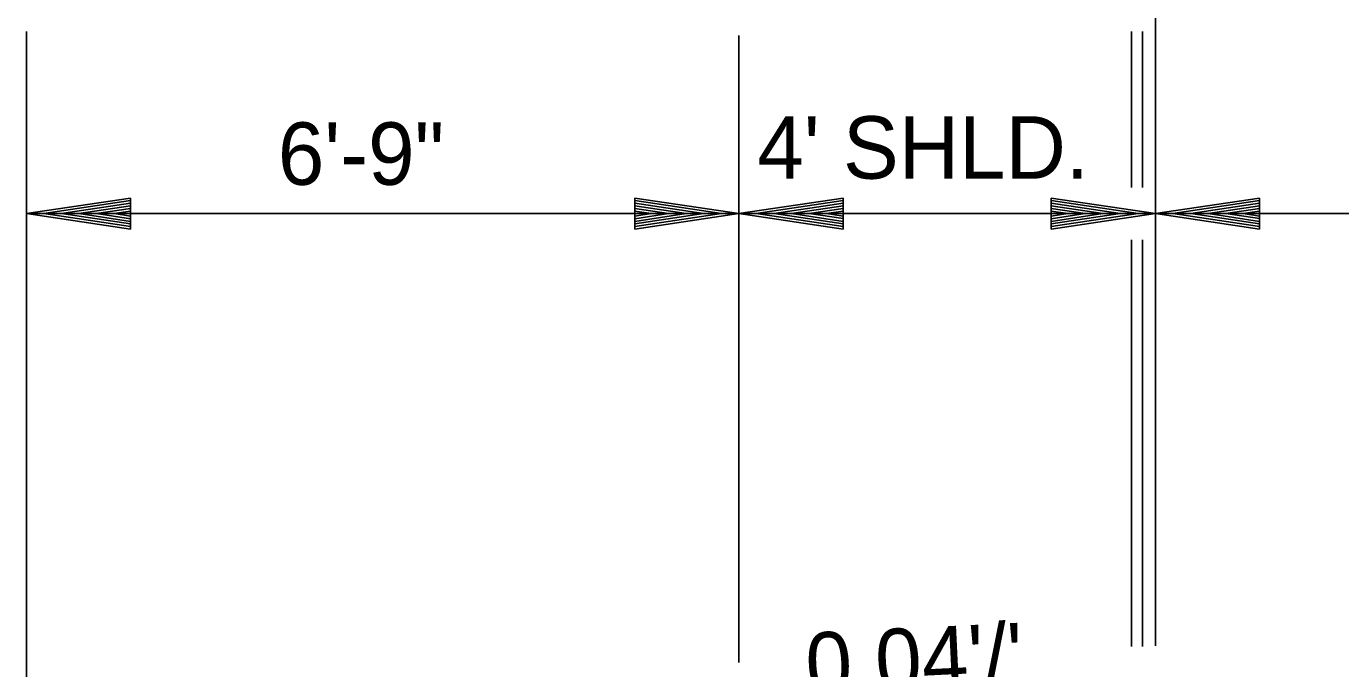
# Model space of a CAD drawing. Extents: x -900 to 15312, y 1857 to 2945.
# Drawn here: x 3845.7 to 3971.9, y 2462.3 to 2524 of the extents above; entities that cross this region are included whole.
import ezdxf

# ---------------------------------------------------------------- set-up
doc = ezdxf.new("R2010")
doc.units = 0
doc.layers.add('R_Annotation', color=7, linetype='Continuous')
doc.layers.add('R_Dimension', color=7, linetype='Continuous')

msp = doc.modelspace()

# ---------------------------------------------------------------- linework, layer by layer
at = {"layer": 'R_Dimension'}
for p, q in [((3954.16, 2506.02), (3954.16, 2531.02)), ((3845.74, 2453.95), (3845.74, 2523.52)), ((3914.16, 2462.9), (3914.16, 2523.15)), ((3951.85, 2508.52), (3951.85, 2523.52)), ((3952.9, 2508.52), (3952.9, 2523.52)), ((3914.16, 2462.9), (3914.16, 2511.02)), ((3855.74, 2507.52), (3845.74, 2506.02)), ((3855.74, 2507.27), (3847.41, 2506.02)), ((3855.74, 2507.02), (3849.13, 2506.02)), ((3855.74, 2506.77), (3850.79, 2506.02)), ((3855.74, 2507.52), (3855.74, 2504.52)), ((3904.16, 2507.52), (3914.16, 2506.02)), ((3904.16, 2507.52), (3904.16, 2504.52)), ((3904.16, 2507.27), (3912.49, 2506.02)), ((3904.16, 2507.02), (3910.77, 2506.02)), ((3904.16, 2506.77), (3909.11, 2506.02)), ((3924.16, 2507.52), (3914.16, 2506.02)), ((3924.16, 2507.27), (3915.83, 2506.02)), ((3924.16, 2507.02), (3917.55, 2506.02)), ((3924.16, 2506.77), (3919.22, 2506.02)), ((3924.16, 2504.52), (3924.16, 2507.52)), ((3944.16, 2507.52), (3954.16, 2506.02)), ((3944.16, 2507.52), (3944.16, 2504.52)), ((3944.16, 2507.27), (3952.49, 2506.02)), ((3944.16, 2507.02), (3950.77, 2506.02)), ((3944.16, 2506.77), (3949.11, 2506.02)), ((3964.16, 2507.52), (3954.16, 2506.02)), ((3964.16, 2507.27), (3955.83, 2506.02)), ((3964.16, 2507.02), (3957.55, 2506.02)), ((3964.16, 2506.77), (3959.22, 2506.02)), ((3964.16, 2504.52), (3964.16, 2507.52)), ((4282.59, 2506.02), (3845.74, 2506.02)), ((3855.74, 2504.52), (3845.74, 2506.02)), ((3855.74, 2504.77), (3847.41, 2506.02)), ((3855.74, 2505.03), (3849.13, 2506.02)), ((3855.74, 2505.28), (3850.79, 2506.02)), ((3855.74, 2506.51), (3852.49, 2506.02)), ((3855.74, 2505.53), (3852.49, 2506.02)), ((3855.74, 2506.26), (3854.16, 2506.02)), ((3855.74, 2505.79), (3854.16, 2506.02)), ((3904.16, 2506.51), (3907.41, 2506.02)), ((3904.16, 2506.26), (3905.74, 2506.02)), ((3904.16, 2504.52), (3914.16, 2506.02)), ((3904.16, 2505.53), (3907.41, 2506.02)), ((3904.16, 2505.03), (3910.77, 2506.02)), ((3904.16, 2504.77), (3912.49, 2506.02)), ((3904.16, 2505.28), (3909.11, 2506.02)), ((3904.16, 2505.79), (3905.74, 2506.02)), ((3924.16, 2504.52), (3914.16, 2506.02)), ((3924.16, 2504.77), (3915.83, 2506.02)), ((3924.16, 2505.03), (3917.55, 2506.02)), ((3924.16, 2505.28), (3919.22, 2506.02)), ((3924.16, 2506.51), (3920.91, 2506.02)), ((3924.16, 2505.54), (3920.91, 2506.02)), ((3924.16, 2506.26), (3922.58, 2506.02)), ((3924.16, 2505.79), (3922.58, 2506.02)), ((3944.16, 2506.51), (3947.41, 2506.02)), ((3944.16, 2506.26), (3945.74, 2506.02)), ((3944.16, 2504.52), (3954.16, 2506.02)), ((3944.16, 2505.53), (3947.41, 2506.02)), ((3944.16, 2505.03), (3950.77, 2506.02)), ((3944.16, 2504.77), (3952.49, 2506.02)), ((3944.16, 2505.28), (3949.11, 2506.02)), ((3944.16, 2505.79), (3945.74, 2506.02)), ((3954.16, 2464.5), (3954.16, 2506.02)), ((3964.16, 2504.52), (3954.16, 2506.02)), ((3964.16, 2504.77), (3955.83, 2506.02)), ((3964.16, 2505.03), (3957.55, 2506.02)), ((3964.16, 2505.28), (3959.22, 2506.02)), ((3964.16, 2506.51), (3960.91, 2506.02)), ((3964.16, 2505.54), (3960.91, 2506.02)), ((3964.16, 2506.26), (3962.58, 2506.02)), ((3964.16, 2505.79), (3962.58, 2506.02)), ((3951.85, 2464.44), (3951.85, 2503.52)), ((3952.9, 2464.44), (3952.9, 2503.52))]:
    msp.add_line(p, q, dxfattribs=at)

# ---------------------------------------------------------------- texts
at = {"layer": 'R_Annotation'}
for s, p in [("4' SHLD.", (3915.93, 2509.38)), ('6\'-9"', (3869.89, 2508.79))]:
    msp.add_text(s, height=6, dxfattribs=at).set_placement(p)
msp.add_text("0.04'/'", height=6, rotation=2.7804, dxfattribs=at).set_placement((3920.71, 2459.72))

doc.saveas('drawing.dxf')
